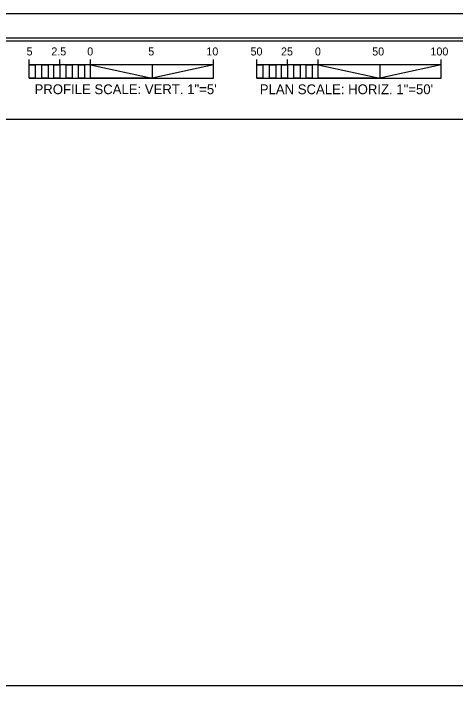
# Model space of a CAD drawing. Extents: x 0 to 4772457, y -312190 to 1506.
# Drawn here: x 1.547 to 2.146, y 0.902 to 1.833 of the extents above; entities that cross this region are included whole.
import ezdxf

# ---------------------------------------------------------------- set-up
doc = ezdxf.new("R2010")
doc.units = 0
for name, color, linetype in [('Exist Solid Lane Line', 7, 'Continuous'), ('Old_Level_63', 7, 'Continuous'), ('Timing Chart CELL', 7, 'Continuous')]:
    doc.layers.add(name, color=color, linetype=linetype)

msp = doc.modelspace()

# ---------------------------------------------------------------- linework, layer by layer
at = {"layer": 'Exist Solid Lane Line'}
for p, q in [((1.56838, 1.74596), (1.56838, 1.77128)), ((1.61005, 1.76405), (1.61005, 1.77132)), ((1.65171, 1.76405), (1.65171, 1.7713)), ((1.81838, 1.76407), (1.81838, 1.77132)), ((1.87729, 1.74591), (1.87729, 1.77124)), ((1.91896, 1.76401), (1.91896, 1.77127)), ((1.96063, 1.76401), (1.96063, 1.77125)), ((2.12729, 1.76403), (2.12729, 1.77127)), ((1.81838, 1.76404), (1.56838, 1.76406)), ((1.62696, 1.76407), (1.62696, 1.74596)), ((1.73505, 1.76407), (1.73505, 1.74596)), ((1.81838, 1.74594), (1.81838, 1.76407)), ((2.12729, 1.764), (1.87729, 1.76401)), ((1.93587, 1.76402), (1.93587, 1.74591)), ((2.04396, 1.76403), (2.04396, 1.74592)), ((2.12729, 1.7459), (2.12729, 1.76403)), ((1.56838, 1.74594), (1.81838, 1.74595)), ((1.87729, 1.7459), (2.12729, 1.74591))]:
    msp.add_line(p, q, dxfattribs=at)
for points in [[(1.56838, 1.76406), (1.57663, 1.76406), (1.57663, 1.74594), (1.56838, 1.74594)], [(1.5857, 1.76407), (1.59395, 1.76405), (1.59395, 1.74594), (1.58572, 1.74594)], [(1.60179, 1.76405), (1.61005, 1.76405), (1.61005, 1.74596), (1.60179, 1.74596)], [(1.6187, 1.76405), (1.62696, 1.76407), (1.62696, 1.74596), (1.61871, 1.74596)], [(1.63521, 1.76407), (1.64346, 1.76407), (1.64346, 1.74594), (1.63521, 1.74596)], [(1.65171, 1.76405), (1.73505, 1.74596), (1.65171, 1.74594)], [(1.81838, 1.76407), (1.73505, 1.74596), (1.81838, 1.74594)], [(1.87729, 1.76401), (1.88554, 1.76401), (1.88554, 1.7459), (1.87729, 1.7459)], [(1.89461, 1.76402), (1.90286, 1.76401), (1.90286, 1.74589), (1.89463, 1.74589)], [(1.91071, 1.76401), (1.91896, 1.76401), (1.91896, 1.74592), (1.91071, 1.74592)], [(1.92762, 1.76401), (1.93587, 1.76402), (1.93587, 1.74591), (1.92762, 1.74591)], [(1.94412, 1.76402), (1.95237, 1.76403), (1.95237, 1.74589), (1.94412, 1.74591)], [(1.96063, 1.76401), (2.04396, 1.74592), (1.96063, 1.7459)], [(2.12729, 1.76403), (2.04396, 1.74592), (2.12729, 1.7459)]]:
    msp.add_lwpolyline(points, close=True, dxfattribs=at)
at = {"layer": 'Old_Level_63'}
for points in [[(0.02749, 0.00833), (2.83333, 0.00833), (2.83333, 1.83333), (0.02749, 1.83333)], [(0.04916, 0.04166), (2.82583, 0.04166), (2.82583, 1.8), (0.04916, 1.8)], [(2.80499, 1.79583), (0.30499, 1.79583), (0.30499, 0.04583), (2.80499, 0.04583)]]:
    msp.add_lwpolyline(points, close=True, dxfattribs=at)
at = {"layer": 'Timing Chart CELL'}
msp.add_lwpolyline([(0.37349, 0.92053), (0.37349, 1.68989), (2.46666, 1.68989), (2.46666, 1.49966), (2.75747, 1.49966), (2.75747, 0.92053)], close=True, dxfattribs=at)

# ---------------------------------------------------------------- texts
at = {"layer": 'Exist Solid Lane Line'}
for s, height, p in [('2.5', 0.010867, (1.59846, 1.77668)), ('0', 0.01087, (1.64717, 1.77666)), ('10', 0.010867, (1.8088, 1.77668)), ('50', 0.010867, (1.86873, 1.77661)), ('25', 0.010867, (1.91013, 1.77663)), ('0', 0.01087, (1.95609, 1.77662)), ('50', 0.010867, (2.03376, 1.77662)), ('100', 0.010867, (2.11282, 1.77664)), ('5', 0.01087, (1.5649, 1.77666)), ('5', 0.01087, (1.72994, 1.77666)), ('PROFILE SCALE: VERT. 1"=5\'', 0.0133333, (1.5757, 1.72407)), ('PLAN SCALE: HORIZ. 1"=50\'', 0.0133333, (1.88124, 1.72403))]:
    msp.add_text(s, height=height, rotation=0.00136, dxfattribs=at).set_placement(p)

doc.saveas('drawing.dxf')
